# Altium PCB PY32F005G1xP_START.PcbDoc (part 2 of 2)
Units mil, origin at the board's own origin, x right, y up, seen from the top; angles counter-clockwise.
Board outline 1771.65 x 3929.06 mil, 2 copper layers (Top Layer, Bottom Layer), stack 21 mil thick; 129 components, 121 nets, 506 pads, 279 vias.
Unrouted connection lines stored in the file: 5.
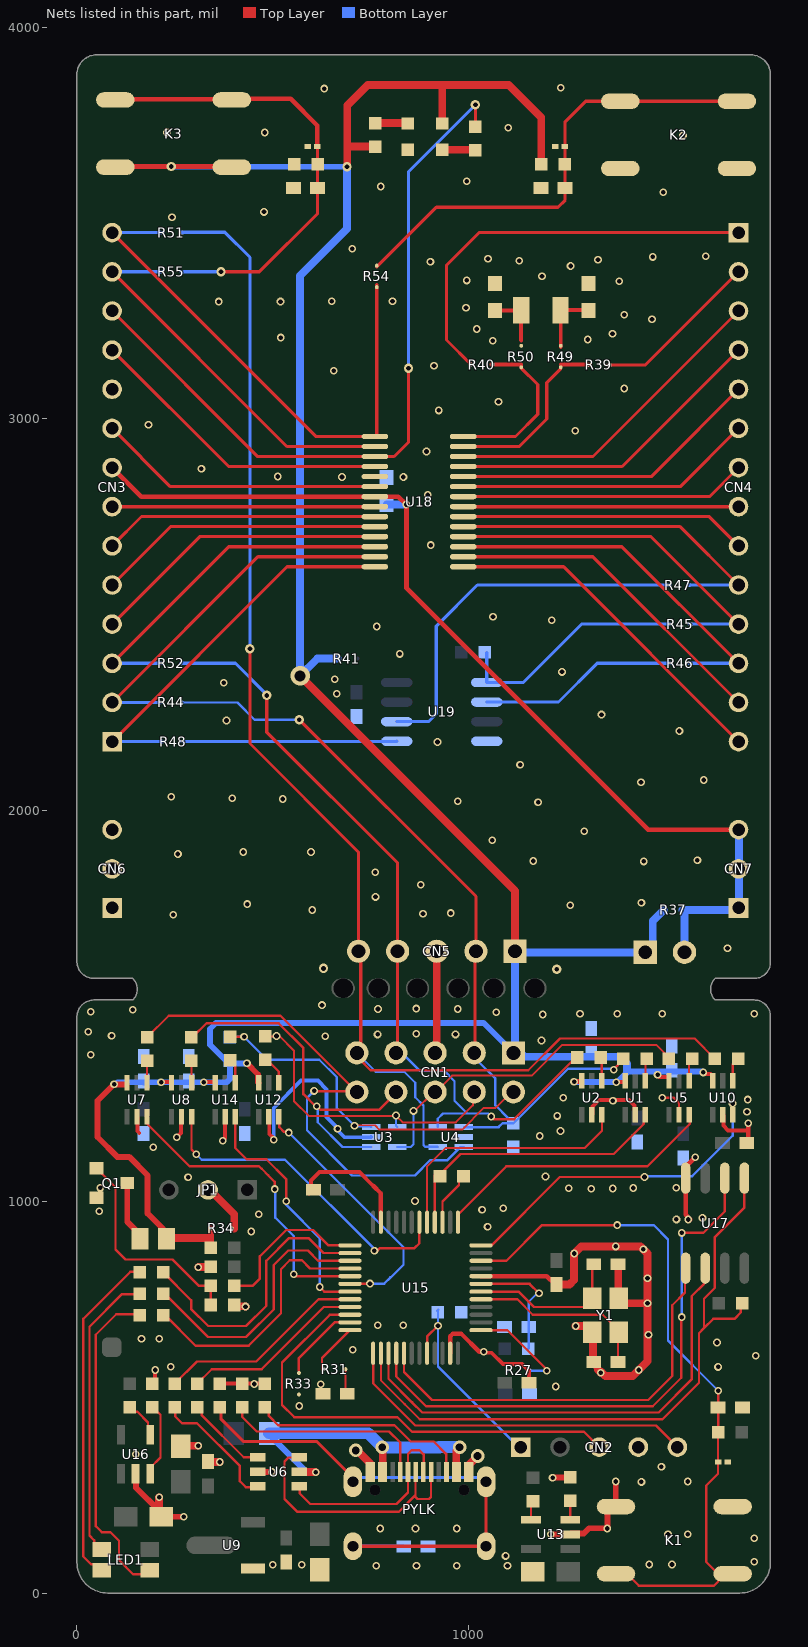
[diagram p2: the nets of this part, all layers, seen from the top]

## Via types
v1: diameter 19.68, hole 11.81, Top Layer to Bottom Layer, 140 vias
v2: diameter 19.68, hole 11.81, Top Layer to Bottom Layer, tented both sides, 114 vias
v3: diameter 24, hole 12, Top Layer to Bottom Layer, tented both sides, 12 vias
v4: diameter 35, hole 20, Top Layer to Bottom Layer, tented both sides, 8 vias
v5: diameter 30, hole 15, Top Layer to Bottom Layer, tented both sides, 2 vias
v6: diameter 40, hole 20, Top Layer to Bottom Layer, tented both sides, 2 vias
v7: diameter 50, hole 28, Top Layer to Bottom Layer, 1 vias

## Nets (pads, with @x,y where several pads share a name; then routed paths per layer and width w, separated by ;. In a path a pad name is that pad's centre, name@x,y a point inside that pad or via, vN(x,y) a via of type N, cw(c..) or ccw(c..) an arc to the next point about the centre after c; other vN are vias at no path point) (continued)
GND: C1.1 C2.1 C3.1 C4.1 C5.1 C6.1 C7.1 C8.1 C9.1 C10.1 C11.1 C12.1 C13.1 C14.1 C15.1 C16.1 C17.1 C18.1 C19.1 C20.1 C21.1 C22.1 C23.1 C24.1 C25.1 C26.1 C27.1 C28.1 C29.1 C30.2 C31.1 CN1.5 CN2.4 CN3.10 CN5.3 CN6.1 CN6.2 CN6.3 K1.3 K1.4 K2.3 K2.4 LED_VDD*.2 PYLK.A1 PYLK.A12 PYLK.B1 PYLK.B12 Q1.2 R1.1 R3.2 R5.1 R8.2 R20.1 R21.1 R25.1 R28.2 R30.1 R33.2 R56.1 U1.2 U2.2 U3.2 U4.2 U5.2 U6.2 U7.2 U8.2 U9.1 U10.2 U11.2 U12.2 U13.2 U14.2 U15.8 U15.23 U15.47 U16.2 U17.4 U18.5 U19.4 U20.2 U21.2 Y1.2 Y1.4 | length 4450.5
  Top Layer w6: v2(1495,1265) 1525,1265 1538.06,1251.94 U5.2@1538.06,1221.69
  Top Layer w10: U7.2@153.55,1216.69 154.54,1215.7 154.54,1180.08 159.36,1175.25 ; R30.1@200,540 v2(200,570) ; C16.1@210,210 210,200 C16.1@215,195 ; v2(255,1164.6) 265.89,1175.49 265.89,1215.32 U8.2@267.26,1216.69 ; C2.1@265,375 C2.1@270,380 ; C3.1@335,336 C3.1@336,335 ; R8.2@365,535 v2@453.95,535 ; v2(372.9,1155.7) 378.59,1161.39 U14.2@378.59,1216.59 ; R20.1@401.52,735.88 R20.1@403.04,737.4 ; v2(453.1,534.15) v2@453.95,535 ; R3.2@480,535 v2@453.95,535 ; U12.2@490.12,1216.69 491.41,1215.4 491.41,1172.62 501.83,1162.2 501.83,1156.83 v2@500,1155 ; C21.1@593.36,1020 603.36,1030 C21.1@604,1030 597.95,1036.05 597.95,1054.14 619.23,1075.42 721.98,1075.42 756.82,1040.58 ; C17.1@628.59,509.5 C17.1@629.59,510.5 ; PYLK.A1@743.31,309.89 PYLK.B12@755.12,309.89 ; PYLK.B1@995.28,309.89 PYLK.A12@1007.09,309.89 ; v2@1039.47,613.56 v2@1039.6,613.69 ; v2@1041.61,614.02 1059.36,614.02 1088.57,584.8 1137.07,584.8 1154.91,566.95 C20.1@1154.87,537.59 ; U2.2@1314.26,1220.75 1317.1,1223.58 1317.1,1242.95 1334.15,1260 v2@1370.02,1260 ; v2(1369.2,1257.6) 1370.02,1258.42 v2@1370.02,1260 ; U1.2@1426.64,1221.69 1424.75,1223.58 1424.75,1245.25 1410,1260 v2@1370.02,1260 ; U10.2@1649.49,1221.69 1651.38,1219.8 1651.38,1193.96 1663.61,1181.72 1715,1181.72
  Top Layer w11: 756.82,1040.58 776.42,1020.98 U15.23@776.42,947.32 ; U15.47@953.58,612.68 953.58,655.91 959.74,662.07 982.08,662.07 1027.87,616.28 v2(1039.35,616.28) ; U15.8@1032.32,809.53 1199.94,809.53 1221.47,788 C22.1@1225.12,788
  Top Layer w12: Q1.2@50.2,1009.8 Q1.2@55.01,1004.99 ; v2(1561.71,954.27) 1566.84,954.27 1555,966.11 1555,1088.88 1579.39,1113.27 v2(1579.39,1113.51) ; C18.1@1711,1150 1715,1154 1715,1181.72 v2(1715,1200)
  Top Layer w15: U16.2@149.48,304.48 150.91,303.04 150.91,269.09 C16.1@210,210 ; C16.1@215,195 v2(272.56,195) ; U6.2@470.66,310.05 472.24,308.47 473.29,309.52 v2(498.08,309.52) ; v2(1210,150) U13.2@1260,150 1262.16,152.16 1294.66,152.16 1308.23,165.74 v2@1354.26,165.74 ; v2(1215,295) R25.1@1260,295 ; v2(1355,165) 1355,209.44 1366.26,220.7 1376.55,220.7 v2(1376.55,285)
  Top Layer w20: C16.1@210,210 v2(210,245) ; C2.1@270,380 273.84,376.16 v2(310,376.16) ; v2(309.83,832.29) 310.59,833.04 341.17,833.04 R21.1@341.93,833.8 ; C3.1@336,335 v2(365,335) ; R20.1@403.04,737.4 403.04,737.12 407.52,732.64 429.94,732.64 v2(430.7,731.87) ; v4(712.08,364.5) 715.53,364.5 PYLK.A1@749.17,330.85 ; CN1.5@915,1380 919.26,1384.26 CN5.3@919.26,1639.56 ; PYLK.A12@1003.89,330.35 v4(1023.55,350) ; C22.1@1220.12,797 1225.12,792 C22.1@1225.12,788 1225.41,788.28 1258.41,788.28 1270.12,800 v2(1270.12,867.57) 1288.1,885.55 1439.57,885.55 1457.58,867.54 v2(1457.58,803.85) 1457.58,740.13 1457.58,592.46 v2(1435.12,570) 1419.85,554.73 1349.89,554.73 v2@1339.64,564.98 ; v2(1273.98,682.29) 1301.06,682.29 Y1.2@1316.66,666.69 1318.39,664.96 1318.39,591.73 C19.1@1320.12,590 1324.12,590 1329.12,585 1329.12,575.5 1330.37,574.25 ; 1330.37,570.63 v2(1337.83,563.18) ; C25.1@1382.12,840 1382.85,839.27 1382.85,754.04 Y1.4@1383.59,753.31 1396.74,740.16 v2(1457.55,740.16)
  Bottom Layer w6: v2@499.26,1157.83 v2(502.89,1157.83)
  Bottom Layer w10: v2(502.89,1157.83) 502.89,1239.49 572.46,1309.06 615.72,1309.06 638,1286.78 638,1215.79 665.89,1187.9 v2(665.89,1185.89) ; v2@665,1183 683.72,1164.28 750.81,1164.28 U3.2@751.54,1165
  Bottom Layer w20: CN1.5@915,1380 CN1.5@921,1386 ; CN5.3@919.26,1639.56 CN5.3@921,1637.82 ; CN5.3@921,1639.56 CN5.3@921,1642.94
  other v1: 500.23,72.73 574.48,72.72 568,478 1223.05,527.77 622.75,533.15 239.93,578.18 704.43,621.59 833.63,683.94 768.47,684.5 445.71,923.68 1049,936 1531.33,954.53 1597.76,958.38 464.86,967.62 1035,979 1089,983 863.55,1001.58 1313.59,1033.06 1368.58,1033.45 1256.66,1033.84 1421.24,1034.63 1530.67,1035.55 284,1062 1197,1064 195,1139 1235.29,1180.47 1227.19,1218.9 1711.69,1229.78 1713.32,1260.65 1186.59,1411.54 634,1422 88.6,1424 768,1427 967,1427 867,1429 29.3,1434.1 1190,1478 1071,1484 769,1492 973,1492 867,1493 626,1502 1661.98,1647.06 246,1733 884,1735 955,1737 601,1745 1260,1757 435,1760 1442,1763 762.85,1778.25 878,1809 761.85,1841.25 1448,1869 1166,1870 1585,1872 258,1888 425,1893 598,1893 1061,1923 1296,1946 1178,2020 973,2023 525.85,2028.25 397,2030 241,2034 1441,2071 1601,2077 1132,2116 921,2174 1539,2202 382,2229 1340,2244 664,2297 375,2325 659,2334 1239,2353 825,2399 766,2469 1213,2485 1063,2494 904,2677 896,2805 677,2851 834,2851 513,2852 318,2872 893,2916 1273,2969 183,2984 924,3021 1077,3043 1398,3077 656,3122 912,3135 1062,3199 1305,3202 521,3207 1368,3217 1021,3229 1469,3254 1398,3265 994,3283 362,3299 520,3299 651,3300 806,3300 1385,3351 996,3353 1188,3364 1261,3390 903,3401 1129.97,3403.49 1331,3406 1050,3408 1471,3413 1606,3415 703,3434 243,3514 478,3528 1498,3578 776,3593 996,3606 1548,3723 230,3731 480,3731 1102,3743 632,3843 1236,3845
  other v2: 765,70 867.5,70 970,70 1100,70 1462.25,73 1520,73 1730,80 1095,95 1730,140 1510,150 1560,150 775,165 865,165 970,165 1442,284 1560,285 1493,323 150,355 1637.74,577.74 1734,606 1635,640 165,650 210,650 1460.12,660 1447.03,878.1 1376.26,885.55 57.3,975.34 60,1035 1182.35,1167.57 1241.94,1264.95 35,1375 1285,1480 1380,1480 1495,1480 1730,1480 35,1485 143,1490
  other v3: 1226,1593.58 630,1595.58
L_USB_CN_DM: PYLK.A7 PYLK.B7 U6.4 | length 510.1
  Top Layer w6: U6.4@568.15,272.6 569.18,271.57 569.18,254.46 596.04,227.6 816.36,227.6 845.67,256.9 845.67,355.67 855,365 875,365 885.71,354.29 885.71,310.57 PYLK.A7@885.04,309.89
L_USB_CN_DP: PYLK.A6 PYLK.B6 U6.6 | length 675.9
  Top Layer w6: U6.6@568.15,347.4 567.26,346.51 540.39,346.51 530.35,336.47 530.35,240.4 563.22,207.53 822.27,207.53 864.95,250.21 ; PYLK.A6@864.95,309.48 864.95,250.21 ; PYLK.B6@904.31,309.48 904.31,245.56 899.06,240.31 870.05,240.31 864.95,245.41 864.95,250.21
LED_BLUE: R9.2 U15.28 | length 675.2
  Top Layer w6: R9.2@220,710 225.04,710 303.26,631.77 438.53,631.77 521.33,714.58 521.33,827.41 543.92,850 575,850 595.79,829.21 U15.28@697.68,829.21
LED_GREEN: R6.2 U15.26 | length 724.3
  Top Layer w6: R6.2@220,820 291.82,748.18 291.82,725.67 335.36,682.13 432.27,682.13 483.48,733.34 483.48,848.48 541.75,906.75 591.91,906.75 630.07,868.58 U15.26@697.68,868.58
LED_RED: R4.2 U15.27 | length 692.2
  Top Layer w6: R4.2@220,765 224.07,765 335.03,654.04 432.13,654.04 502.68,724.59 502.68,837.68 540,875 590,875 616.1,848.9 U15.27@697.68,848.9
NetC1_2: C1.2 PYLK.1 PYLK.2 PYLK.3 PYLK.4 R8.1 | length 1425.4
  Top Layer w8: R8.1@365,475 368.29,471.71 368.29,443.87 424.64,387.52 611.97,387.52 705.12,294.37 PYLK.1@705.12,284.29 ; PYLK.3@705.12,119.73 PYLK.4@1045.28,119.73 PYLK.2@1045.28,284.29
  Bottom Layer w8: PYLK.3@705.12,119.73 834.27,119.73 C1.2@835,119 ; PYLK.1@716.04,295.21 PYLK.2@1034.36,295.21
  Bottom Layer w20: PYLK.1@705.12,284.29 PYLK.1@716.04,295.21 ; PYLK.2@1034.36,295.21 PYLK.2@1045.28,284.29
NetC17_2: C17.2 R31.2 | length 64.1
  Top Layer w6: R31.2@686.21,571.75 686.21,513.88 C17.2@690.59,509.5
NetC28_2: C28.2 K2.1 K2.2 R42.2 R54.1 U20.1 | length 1213.2
  Top Layer w8: R54.1@766,3387.75 918.25,3540 1229,3540 1247,3558 C28.2@1247,3589 1247,3649 R42.2@1246,3650 1246.3,3650.3 U20.1@1246.3,3695 1246.3,3757.3 1299.7,3810.7 K2.1@1388,3810.7 K2.2@1686,3810.7
NetC29_2: C29.2 R49.1 Y2.1 | length 165.9
  Top Layer w10: R49.1@1236,3182.76 1236,3276.2 Y2.1@1235.2,3277 C29.2@1306.5,3277
NetC30_1: C30.1 R50.1 Y2.2 | length 144.1
  Top Layer w10: C30.1@1068,3276.5 1134.3,3276.5 Y2.2@1134.81,3277 1134.81,3200.19 1135,3200
NetC31_2: C31.2 K3.3 K3.4 R55.1 R56.2 U21.1 | length 1188.1
  Top Layer w8: v3(368,3375) 466,3375 615,3524 C31.2@615,3589 R56.2@615,3650 U21.1@615,3695
  Top Layer w12: K3.4@92,3815.59 390,3815.59 391.76,3817.35 545.65,3817.35 614.3,3748.7 U21.1@614.3,3695
  Bottom Layer w8: R55.1@264.75,3375 v3(368,3375)
NetCN4_1: CN4.1 R40.2 | length 1060.5
  Top Layer w8: R40.2@1007,3138 944,3201 944,3392 1027,3475 CN4.1@1690,3475
NetCN4_2: CN4.2 R39.2 | length 434.6
  Top Layer w8: R39.2@1354.03,3136.97 1451.97,3136.97 CN4.2@1690,3375
NetLED1_2: LED1.2 R9.1 | length 846.1
  Top Layer w6: R9.1@160,710 157.67,712.33 100.33,712.33 48,660 48,171 63.8,155.2 85.86,155.2 107.53,133.53 107.53,84.16 143.82,47.87 175.08,47.87 LED1.2@186.02,58.82
NetLED1_3: LED1.3 R6.1 | length 884.3
  Top Layer w6: LED1.3@44.28,58.52 LED1.3@58.98,43.82 ; LED1.3@63.98,58.82 49.28,73.52 36.09,73.52 16,93.61 16,700.34 136.59,820.93 159.07,820.93 R6.1@160,820
NetLED1_4: LED1.4 R4.1 | length 755.1
  Top Layer w6: LED1.4@56.66,98.5 44.36,110.81 44.36,134.74 32,147.09 32,680.34 115.39,763.73 158.73,763.73 R4.1@160,765
NetLED_PA1_2: LED_PA1.2 R53.1 | length 84
  Top Layer w20: LED_PA1.2@933,3687 R53.1@1017,3687
NetLED_VDD*_1: LED_VDD*.1 R38.1 | length 83
  Top Layer w20: R38.1@762,3754.89 LED_VDD*.1@845,3754.89
NetPYLK_A5: PYLK.A5 R1.2 | length 530.3
  Top Layer w6: R1.2@422.49,474.99 422.49,449.82 459.51,412.79 797.58,412.79 825.99,384.38 PYLK.A5@825.99,309.89
NetPYLK_B5: PYLK.B5 R3.1 | length 566
  Top Layer w6: R3.1@480,475 490.31,464.69 490.31,452.34 513.85,428.8 811.11,428.8 852.66,387.24 911.55,387.24 943.17,355.62 943.17,310.82 PYLK.B5@944.1,309.89
NetQ1_1: Q1.1 R19.1 R20.2 | length 559
  Top Layer w6: Q1.1@50,1084.8 51.97,1084.8 63.72,1073.06 63.72,1071.23 98.46,1036.49 98.46,877.34 123.86,851.94 244.45,851.94 311.61,784.78 R19.1@341.53,784.78 ; R20.2@341.52,735.88 R19.1@341.52,784.77
NetQ1_3: Q1.3 R15.1 | length 166.5
  Top Layer w6: Q1.3@125.49,1044.15 Q1.3@128.74,1047.4 ; R15.1@161.54,905 R15.1@161.54,910.91
  Top Layer w15: Q1.3@128.74,1047.4 128.74,948.28 161.54,915.49 R15.1@161.54,905
NetR2_1: R2.1 U1.4 | length 57.9
  Top Layer w6: U1.4@1452.23,1308.31 1452.23,1362.02 R2.1@1455.21,1365
NetR7_1: R7.1 U2.4 | length 57.8
  Top Layer w6: R7.1@1338.06,1365 1340.8,1362.27 U2.4@1340.8,1308.31
NetR10_1: R10.1 U5.4 | length 60.3
  Top Layer w6: U5.4@1563.66,1308.31 1563.66,1356.3 R10.1@1572.35,1365
NetR11_1: R11.1 U6.3 | length 332.9
  Top Layer w6: R11.1@250,475 250.77,474.23 250.77,451.69 268.41,434.05 306.8,434.05 416.24,324.61 416.24,285.87 431.63,270.48 459.74,270.48 U6.3@461.53,272.28
NetR12_1: R12.1 U6.1 | length 227.7
  Top Layer w6: R12.1@308.75,480 319.15,469.6 319.15,453.68 426,346.83 U6.1@471.97,346.83
NetR13_1: R13.1 U7.4 | length 59
  Top Layer w6: R13.1@173.55,1360 179.14,1354.41 U7.4@179.14,1303.31
NetR14_1: R14.1 U8.4 | length 60.8
  Top Layer w6: R14.1@280.94,1360.02 R14.1@290.82,1350.14 ; U8.4@292.85,1303.31 R14.1@292.86,1350.12
NetR18_1: R18.1 U10.4 | length 62.7
  Top Layer w6: U10.4@1675.08,1308.31 1675.08,1350.59 R18.1@1689.49,1365
NetR22_1: R22.1 U12.4 | length 75.3
  Top Layer w6: R22.1@481.63,1362.11 485.62,1362.11 515.71,1332.03 U12.4@515.71,1303.31
NetR24_2: R24.2 U13.4 | length 49.6
  Top Layer w6: U13.4@1160,187.5 1160,230 R24.2@1165,235
NetR25_2: R25.2 U13.3 | length 47.5
  Top Layer w6: U13.3@1260,187.5 R25.2@1260,235
NetR26_1: R26.1 U14.4 | length 62.8
  Top Layer w6: R26.1@391.2,1360.7 404.28,1347.62 U14.4@404.28,1303.31
NetR27_2: R27.2 U15.1 | length 263.8
  Top Layer w6: U15.1@1032.32,671.73 1099.27,671.73 1200,571 v1(1200,568)
  Bottom Layer w6: R27.2@1149.03,569.03 1150.05,568 v1(1200,568)
NetR29_2: R29.2 U16.4 | length 96.1
  Top Layer w6: R29.2@135,475 147,463 154.44,463 181.5,435.94 181.5,411 U16.4@187.5,405
NetR30_2: R30.2 U16.3 | length 190
  Top Layer w6: U16.3@187.5,305 187.5,320 213.56,346.06 213.56,455.68 207.24,462 206,462 R30.2@193,475
NetR31_1: R31.1 U15.36 | length 129.6
  Top Layer w6: R31.1@626.21,571.75 626.21,600.26 U15.36@697.68,671.73
NetR33_1: R33.1 U15.35 | length 201.4
  Top Layer w6: 566.96,567.4 566.96,600.38 658,691.42 U15.35@697.68,691.42
NetR43_1: R43.1 R45.1 U19.1 | length 609
  Bottom Layer w8: R43.1@1047,2403 U19.1@1047,2326 1140,2326 1289,2475 R45.1@1517.24,2475
NetR46_1: R46.1 U19.2 | length 511.2
  Bottom Layer w8: U19.2@1047,2276 1230,2276 1329,2375 R46.1@1517.24,2375
NetR47_2: R47.2 U19.6 | length 974.7
  Bottom Layer w8: U19.6@817,2226 898,2226 918,2246 918,2470 1022.97,2574.97 R47.2@1515.97,2574.97
NetR48_2: R48.2 U19.5 | length 551.4
  Bottom Layer w8: R48.2@266.02,2175.03 816.02,2175.03 U19.5@817,2176
OSCIN32: R39.1 R49.2 U18.27 | length 459.2
  Top Layer w8: U18.27@986.83,2928.75 1129.75,2928.75 1200,2999 1200,3092 R49.2@1235.5,3127.5
  Top Layer w10: R49.2@1235.97,3137.98 1308.27,3137.98 R39.1@1309.25,3137
OSCOUT32: R40.1 R50.2 U18.28 | length 434.3
  Top Layer w8: U18.28@986.83,2954.34 1120.34,2954.34 1177,3011 1177,3087 1134.96,3129.04 R50.2@1134.97,3137.98
  Top Layer w10: R40.1@1058.75,3138 R50.2@1134.97,3137.98
PA0: CN3.13 R55.2 U18.2 | length 986
  Top Layer w8: CN3.13@90,3375 536.25,2928.75 U18.2@761.18,2928.75
  Bottom Layer w8: CN3.13@90,3375 R55.2@219.97,3374.97
PA1: CN3.12 R53.2 U18.3 | length 1915.4
  Top Layer w8: CN3.12@90,3275 462,2903 U18.3@761.18,2903 ; U18.3@761.18,2903.16 810.16,2903.16 847.31,2940.31 847.31,3036.69 847,3037 v3(847,3129) ; R53.2@1018,3746 v3(1018,3802)
  Bottom Layer w8: v3(847,3129) 847,3631 v3(1018,3802)
PA2: CN3.11 U18.4 | length 794.4
  Top Layer w8: CN3.11@90,3175 387.43,2877.57 U18.4@761.18,2877.57
PA3: CN3.9 U18.6 | length 732.7
  Top Layer w8: CN3.9@90,2975 238.61,2826.39 U18.6@761.18,2826.39
PA4: CN3.7 U18.8 | length 671.2
  Top Layer w8: CN3.7@90,2775 U18.8@761.18,2775
PA5: CN3.6 U18.9 | length 704.3
  Top Layer w8: CN3.6@90,2675 165,2750 U18.9@763.24,2750
PA6: CN3.5 U18.10 | length 726.6
  Top Layer w8: CN3.5@90,2575 239,2724 U18.10@754.88,2724
PA7: CN3.4 U18.11 | length 763.7
  Top Layer w8: CN3.4@90,2475 313.43,2698.43 U18.11@761.18,2698.43
PB0: CN4.10 R47.1 U18.19 | length 894.1
  Top Layer w8: U18.19@986.83,2724.02 1540.98,2724.02 CN4.10@1690,2575
  Bottom Layer w8: R47.1@1560.75,2575 CN4.10@1690,2575
PB1: CN4.11 R45.2 U18.18 | length 923.7
  Top Layer w8: U18.18@986.83,2698.43 1466.57,2698.43 CN4.11@1690,2475
  Bottom Layer w8: R45.2@1562.02,2475.03 CN4.11@1690,2475
PB2: CN4.12 R46.2 U18.17 | length 954.5
  Top Layer w8: U18.17@986.83,2672.84 1392.16,2672.84 CN4.12@1690,2375
  Bottom Layer w8: R46.2@1562.02,2375.03 CN4.12@1690,2375
PB3: CN3.1 R48.1 U18.14 | length 987.4
  Top Layer w8: CN3.1@90,2175 536.66,2621.66 U18.14@761.18,2621.66
  Bottom Layer w8: CN3.1@90,2175 R48.1@221.24,2175
PB4: CN4.14 U18.15 | length 888.2
  Top Layer w8: U18.15@986.83,2621.66 1243.34,2621.66 CN4.14@1690,2175
PB5: CN4.13 U18.16 | length 857.4
  Top Layer w8: U18.16@986.83,2647.25 1317.75,2647.25 CN4.13@1690,2275
PC0-NRST: CN3.14 R51.2 R54.2 U18.1 | length 1409.9
  Top Layer w8: CN3.14@90,3475 611,2954 U18.1@761.18,2954 ; U18.1@761.18,2954.34 763.43,2954.34 765.97,2956.88 R54.2@765.97,3342.97
  Bottom Layer w8: CN3.14@90,3475 R51.2@220.97,3474.97
PC1: CN4.3 U18.26 | length 857.2
  Top Layer w8: U18.26@986.83,2903.16 1318.16,2903.16 1391,2976 CN4.3@1690,3275
PC2: CN4.4 U18.25 | length 826.4
  Top Layer w8: U18.25@986.83,2877.57 1392.57,2877.57 1441,2926 CN4.4@1690,3175
PC3: CN4.5 U18.24 | length 795.5
  Top Layer w8: U18.24@986.83,2851.98 1466.98,2851.98 1491,2876 CN4.5@1690,3075
PC4: CN4.6 U18.23 | length 764.7
  Top Layer w8: U18.23@986.83,2826.39 1541.39,2826.39 CN4.6@1690,2975
PC5: CN4.7 U18.22 | length 733.9
  Top Layer w8: U18.22@986.83,2800.8 1615.8,2800.8 CN4.7@1690,2875
PC6: CN4.8 U18.21 | length 700
  Top Layer w8: U18.21@990,2775 CN4.8@1690,2775
PC7: CN4.9 U18.20 | length 734.1
  Top Layer w8: U18.20@986.83,2749.61 1615.39,2749.61 1689.5,2675.5 CN4.9@1690,2675
PYLK_BOOT0: CN2.1 R28.1 U15.44 | length 514.4
  Top Layer w6: U15.44@894.53,612.68 894.53,655.07 v2(922.21,682.75)
  Bottom Layer w6: R28.1@923.26,724.4 920.49,721.63 922.21,719.9 v2(922.21,682.75) 922.21,578.79 CN2.1@1124,377
PYLK_KEY: C6.2 K1.1 K1.2 R16.1 U11.1 U15.10 | length 1804.3
  Top Layer w6: U15.10@1032.32,848.9 1097.14,848.9 1188.24,940 v2(1380,940) ; K1.2@1376.55,49 1405.25,49 1435.5,18.75 1627.36,18.75 1639.02,30.41 1639.02,34.51 K1.1@1653.51,49 ; v2(1638,517) C6.2@1638,474 R16.1@1638,411 1637.7,410.7 U11.1@1637.7,335 1637.7,304.7 1607.3,274.3 1607.3,80 1638.3,49 K1.1@1653.51,49 ; K1.1@1674.55,49 K1.1@1653.51,49
  Bottom Layer w6: v2(1380,940) 1473.52,940 1510,903.52 1510,645 v2(1638,517)
PYLK_NRST: C24.2 R36.1 U15.7 | length 313.8
  Top Layer w6: U15.7@1032.32,789.84 1156.36,789.84 v2(1180.4,765.8)
  Bottom Layer w6: R36.1@1153,624 1154.12,625.12 C24.2@1154.12,680 1154.12,744 1175.92,765.8 v2(1180.4,765.8)
PYLK_OSCIN: C19.2 U15.5 Y1.3 | length 465.6
  Top Layer w6: U15.5@1032.32,750.47 1125.05,750.47 1164.42,711.1 1343.11,711.1 1383.59,670.63 Y1.3@1383.59,666.69 1382.12,665.22 C19.2@1382.12,590
PYLK_OSCOUT: C25.2 U15.6 Y1.1 | length 399.8
  Top Layer w6: U15.6@1032.32,770.16 1127.99,770.16 1167.36,730.79 1297.03,730.79 1316.66,750.41 Y1.1@1316.66,753.31 1316.66,836.54 C25.2@1320.12,840
PYLK_SPI_CS: R35.1 U15.38 U17.1 | length 1667.6
  Top Layer w5: U15.38@776.42,612.68 776.42,543.62 837.66,482.38
  Top Layer w6: 837.66,482.38 875.95,444.09 1495.51,444.09 1588.88,537.47 1588.88,663.88 1601.77,676.77 ; R35.1@1700,740 1695.62,735.62 1695.62,716.69 1679.36,700.42 1625.42,700.42 1601.77,676.77 ; U17.1@1705,1060 1705,985 1629.69,909.69 1629.69,780.01 1601.77,752.09 1601.77,676.77
PYLK_SPI_MISO: U15.40 U17.2 | length 1437.2
  Top Layer w6: U15.40@815.79,612.68 815.79,553.3 891.8,477.3 1471,477.3 1543.9,550.2 1543.9,703.9 v2(1545,705) ; v2(1545,920) 1600,920 1655,975 U17.2@1655,1060
  Bottom Layer w6: v2(1545,705) v2(1545,920)
PYLK_SPI_MOSI: U15.41 U17.5 | length 1077.9
  Top Layer w6: U15.41@835.47,612.68 835.47,564.49 906.66,493.3 1459.42,493.3 1520.53,554.41 1520.53,735.09 1553.13,767.69 1553.13,828.13 U17.5@1555,830
PYLK_SPI_SCK: U15.39 U17.6 | length 1208.9
  Top Layer w6: U15.39@796.1,612.68 796.1,547.36 856.32,487.14 882.17,461.3 1486.07,461.3 1570.21,545.44 1570.21,758.06 1601.94,789.79 1601.94,826.94 U17.6@1605,830
SWCLK: CN3.3 R52.2 U18.12 | length 924.5
  Top Layer w8: CN3.3@90,2375 387.84,2672.84 U18.12@761.18,2672.84
  Bottom Layer w8: CN3.3@90.03,2374.97 R52.2@219.97,2374.97
SWD_SCK: CN2.5 U15.37 | length 921.6
  Top Layer w6: U15.37@756.73,612.68 756.73,535.75 864.48,428 1479,428 CN2.5@1534,373
SWD_SDA: CN2.3 U15.34 | length 1187.1
  Top Layer w6: U15.34@697.68,711.1 646.11,711.1 524.05,589.04 524.05,480.71 555.57,449.2 818.75,449.2 855.95,412 1295,412 CN2.3@1334,373
SWDIO: CN3.2 R44.2 U18.13 | length 955.4
  Top Layer w8: CN3.2@90,2275 462.25,2647.25 U18.13@761.18,2647.25
  Bottom Layer w8: CN3.2@90,2275 R44.2@219.97,2274.97
T_RESET: CN1.9 CN5.5 R18.2 R51.1 U4.4 | length 3737
  Top Layer w6: CN1.9@715,1380 CN1.9@725,1390 ; CN5.5@719.26,1639.56 CN5.5@725,1633.82 ; CN1.9@722.78,1362.78 750.2,1335.36 1152.91,1335.36 1233.99,1416.44 1578.06,1416.44 R18.2@1629.49,1365
  Top Layer w8: v3(442,2412) 442,2170 719.26,1892.74 CN5.5@719.26,1639.56 ; CN1.9@725,1390 CN5.5@725,1633.82
  Bottom Layer w6: CN1.9@715,1380 763.22,1331.78 836.02,1331.78 864.1,1303.69 864.1,1266.42 885.15,1245.37 885.15,1144.31 889.61,1139.85 921.09,1139.85 U4.4@921.54,1139.41
  Bottom Layer w8: R51.1@264.75,3476 378,3476 442,3412 v3(442,2412) ; CN1.9@715,1380 CN1.9@724.04,1389.04 ; CN5.5@719.26,1639.56 CN5.5@724.15,1644.45
T_RESETa: U10.3 U15.12 | length 870.1
  Top Layer w6: U15.12@1032.32,888.27 1058.79,888.27 1233.47,1062.96 1321.53,1062.96 v2(1449.91,1062.96) ; v2(1674.82,1250.7) 1675.08,1250.44 U10.3@1675.08,1221.69
  Bottom Layer w6: v2(1449.91,1062.96) 1451.65,1064.7 1571.4,1064.7 1674.82,1168.11 v2(1674.82,1250.7)
T_RTCK_DTRa: U5.3 U15.13 | length 731.2
  Top Layer w6: U15.13@973.27,947.32 973.27,966.57 1096.7,1090 1456.99,1090 1565.18,1198.19 1565.18,1220.16 U5.3@1563.66,1221.69
T_RTCK_VCP_DTR: CN1.6 R10.2 U3.5 | length 868.3
  Top Layer w5: v2(859.81,1231.67) 863.24,1231.67 911.57,1280 CN1.6@915,1280 916.63,1280 958.49,1321.86 1161.73,1321.86 1240.3,1400.44 1479.98,1400.44 1500.35,1380.07 1500.35,1377 R10.2@1512.35,1365
  Bottom Layer w6: U3.5@818.46,1139.41 852.51,1139.41 859.81,1146.71 v2(859.81,1231.67)
T_TCK_SWCLK: CN1.7 CN5.4 R7.2 R52.1 U4.5 | length 2038.8
  Top Layer w6: v2(1058.5,1217.32) 1065.14,1210.69 1116.96,1210.69 1271.28,1365 R7.2@1278.06,1365
  Top Layer w8: v3(485,2293) 485,2199 819.26,1864.74 CN5.4@819.26,1639.56 819.26,1384.26 CN1.7@815,1380
  Bottom Layer w6: CN1.7@822.5,1387.5 875.47,1334.53 937.65,1334.53 964.6,1307.57 964.6,1257.54 997.14,1225 ; U4.5@921.54,1190.59 921.54,1211.54 935,1225 997.14,1225 ; v2(1058.5,1217.32) 1050.82,1225 997.14,1225
  Bottom Layer w8: R52.1@264.75,2375 405.07,2375 485,2295.07 v3(485,2293) ; CN1.7@815,1380 CN1.7@817.79,1382.79 ; CN5.4@817.79,1638.1 CN5.4@819.26,1639.56
T_TCK_SWCLKa: U2.3 U15.17 | length 668.1
  Top Layer w5: U15.17@894.53,947.32 894.53,1089.76 941.77,1137
  Top Layer w6: 941.77,1137 1047.62,1137 1297.43,1137 1341.41,1180.98 1341.41,1221.08 U2.3@1340.8,1221.69
T_TDI_VCP_TX: CN1.4 R22.2 U3.4 | length 783.1
  Top Layer w5: R22.2@481.63,1422.11 517.9,1422.11 554.54,1385.48 554.54,1256.62 592.29,1218.86 v2@815,1218.86 ; R22.2@481.63,1425.11 R22.2@483.13,1423.61 ; v2@815.02,1218.86 831.78,1202.11 967.76,1202.11 1011.56,1245.9 1011.56,1276.56 CN1.4@1015,1280
  Bottom Layer w5: v2@815.06,1219.94 815.06,1194 U3.4@818.46,1190.59
  other v1: 509.96,1422.98
  other v2: 815,1220
T_TDI_VCP_TXa: U12.3 U15.30 | length 672.4
  Top Layer w6: U12.3@515.71,1216.69 516.93,1215.47 516.93,1190.37 529.24,1178.06 539.56,1178.06 v2(541.31,1176.31) ; U15.30@697.68,789.84 748.02,789.84 v2(748.76,790.58)
  Bottom Layer w6: v2(541.31,1176.31) 834.09,883.53 834.09,838.92 801.56,806.38 800.71,806.38 784.91,790.58 v2(748.76,790.58)
T_TDO_SWO: CN1.10 R13.2 U4.3 | length 1333.3
  Top Layer w6: R13.2@179.66,1420.08 234.47,1474.9 520.1,1474.9 CN1.10@708.51,1286.49 ; v2(605.87,1282.75) 606.54,1282.08 704.1,1282.08 CN1.10@708.51,1286.49 ; CN1.10@715,1280 CN1.10@708.51,1286.49
  Bottom Layer w6: v2(605.87,1282.75) 587.83,1264.72 587.83,1182.08 703.06,1066.86 863.29,1066.86 902.42,1105.99 946.45,1105.99 979.88,1139.41 U4.3@988.46,1139.41 U4.3@986.15,1137.1
T_TDO_SWOa: U7.3 U15.29 | length 807.7
  Top Layer w6: U7.3@179.14,1216.69 179.14,1198.86 287.46,1090.54 465.08,1090.54 471.63,1084 472.01,1084 489,1067.01 489,1066.63 504.93,1050.7 504.93,1032.69 v2(505.62,1032) ; v2(553.88,814.33) 558.68,809.53 641.55,809.53 U15.29@697.68,809.53
  Bottom Layer w6: v2(505.62,1032) 506.95,1030.68 506.95,958.93 553.88,912 v2(553.88,814.33)
T_TMS_SWDIO: CN1.3 CN5.2 R2.2 R5.2 R44.1 U4.1 | length 2040.9
  Top Layer w6: CN1.3@1015,1380 CN1.3@1017.13,1382.13 ; CN5.2@1017.13,1637.43 CN5.2@1019.26,1639.56 ; CN1.3@1019.37,1366.19 CN1.3@1025.56,1360 ; v2@1371.62,1338.31 1382.21,1348.9 1382.21,1352 R2.2@1395.21,1365
  Top Layer w8: v3(568,2231) 1019.26,1779.74 CN5.2@1019.26,1639.56 ; CN1.3@1017.13,1382.13 CN5.2@1017.13,1637.43
  Bottom Layer w6: R44.1@264.75,2275 410,2275 454,2231 v3(568,2231) ; U4.1@988.77,1190.29 1077.29,1190.29 1087,1200 R5.2@1115,1200 1254.25,1339.25 1369.25,1339.25 v2(1371.43,1337.07) ; CN1.3@1015,1380 CN1.3@1019,1384 ; CN5.2@1019,1639.3 CN5.2@1019.26,1639.56 ; CN5.2@1019,1639.56 CN5.2@1019,1644.94 ; CN1.3@1023.59,1359.7 1068.86,1314.42 1068.86,1246.14 R5.2@1101.08,1213.92
T_TMS_SWDIOa: R32.1 U1.3 U15.16 | length 723.8
  Top Layer w6: U15.16@914.21,947.32 R32.1@914.21,1067.37 ; R32.1@927.46,1064.37 927.46,1068.99 980.12,1121.65 1036.7,1121.65 1371.22,1121.65 1448.34,1198.77 1448.34,1217.8 U1.3@1452.23,1221.69
T_TMS_SWDIOa_OUT: R32.2 U15.15 | length 143.2
  Top Layer w6: U15.15@933.9,947.32 933.9,1000.64 975.82,1042.56 R32.2@975.82,1073.16
T_TRST_RTSa: U8.3 U15.18 | length 840.3
  Top Layer w6: U8.3@292.85,1216.69 292.86,1132.86 v2(304.82,1120.9) ; v2(759.92,874.35) 763.83,870.44 774.54,881.16 862.39,881.16 874.84,893.6 U15.18@874.84,947.32
  Bottom Layer w6: v2(304.82,1120.9) 318.81,1106.91 531.65,1106.91 759.92,878.64 v2(759.92,874.35)
T_TRST_VCP_RTS: CN1.8 R14.2 U3.1 | length 935
  Top Layer w6: R14.2@292.3,1420.1 295.54,1420.1 331.24,1455.8 515.25,1455.8 578.58,1392.47 578.58,1274.56 609.4,1243.73 v2(612.86,1243.73) 621.6,1235 772.67,1235 820,1282.33 CN1.8@820,1290
  Bottom Layer w6: v2(612.86,1243.73) 615,1241.6 615,1202.6 678.19,1139.41 U3.1@751.54,1139.41
T_VCP_RX: CN1.2 R23.1 R26.2 U3.3 | length 1000.9
  Top Layer w5: v2(708.97,1193.74) 710.23,1195 761.42,1195 772.45,1183.97 983.91,1183.97 1039.3,1239.36 1069.36,1239.36 CN1.2@1120,1290
  Top Layer w6: R26.2@391.2,1420.7 426.7,1420.7 v1(427,1421) ; R26.2@391.2,1431.85 R26.2@391.32,1431.97
  Bottom Layer w6: R23.1@391,1420 392,1421 v1(427,1421) 485.72,1362.28 619.26,1362.28 664.05,1317.5 664.05,1238.66 v2(708.97,1193.74) 708.23,1193 708.23,1191.77 750.36,1191.77 U3.3@751.54,1190.59
T_VCP_RXa: U14.3 U15.31 | length 636
  Top Layer w6: U14.3@404.28,1216.69 404.28,1137.29 433.27,1108.3 483.54,1108.3 534.4,1057.43 534.4,1001.38 v2(535,1000.78) ; v2(620.4,781.75) 631.99,770.16 U15.31@697.68,770.16
  Bottom Layer w6: v2(535,1000.78) 535,991.42 620.4,906.02 v2(620.4,781.75)
TVDD: C12.2 C13.2 C14.2 C15.2 CN1.1 CN5.1 JP2.1 K3.1 K3.2 LED_PA1.1 R15.2 R17.2 R23.2 R34.2 R37.1 R38.2 R41.1 R42.1 U1.6 U2.6 U5.6 U7.6 U8.6 U10.6 U12.6 U14.6 | length 7774.8
  Top Layer w6: U8.6@241.67,1303.31 U8.6@244.56,1306.2 ; U14.6@353.1,1303.31 U14.6@355.99,1306.2
  Top Layer w10: v2(215,1305) 239.98,1305 U8.6@241.67,1303.31 ; v1@325,1305 351.41,1305 U14.6@353.1,1303.31 ; v1(1377.88,1305.09) 1399.07,1305.09 1399.16,1305 1401.05,1306.89 U1.6@1401.05,1308.31 ; v2(1483.29,1324.06) 1488.61,1318.74 1512.47,1318.74 U5.6@1512.47,1308.31 ; v2@1608.68,1326.1 1618.91,1326.1 1623.9,1321.1 U10.6@1623.9,1308.31
  Top Layer w12: K3.2@92,3643.89 v3(241,3643.89) K3.1@390,3643.89 ; v2@1270.9,1306.9 U2.6@1289.01,1306.9
  Top Layer w15: v2(95,1300) 52.5,1257.5 52.5,1164.78 103.07,1114.2 133.42,1114.2 180.53,1067.09 180.53,969.95 220.52,929.96 220.52,912.95 R15.2@228.46,905 R15.2@230.24,906.78 ; v2@95.63,1299.37 U7.6@127.35,1299.37 ; 338.07,906.78 342.08,902.77 ; R17.2@342.08,874.02 342.08,902.77 ; R34.2@342.08,931.52 342.08,902.77 ; v1(434.28,1353.05) 462.84,1324.49 462.84,1305 U12.6@464.53,1303.31 ; v2(1270,1306) v2@1270.9,1306.9
  Top Layer w20: R15.2@230.24,906.78 338.07,906.78 ; v7(570,2343) 1119.26,1793.74 CN5.1@1119.26,1639.56 ; v3(690,3643) 690.77,3643.77 690.77,3694.89 ; R38.2@762,3694.89 690.77,3694.89 ; LED_PA1.1@933,3754 933,3852 ; R42.1@1186,3650 1186,3769 1103,3852 933,3852 ; 690.77,3694.89 690.77,3799.77 743,3852 933,3852
  Bottom Layer w15: v2(95,1300) 98.79,1300 103.67,1304.88 C15.2@168.87,1304.88 ; C15.2@170,1303.74 C15.2@168.87,1304.88 ; v2@214.88,1304.88 C15.2@168.87,1304.88 ; v2(215,1305) v1(323.77,1305) 383,1305 391,1313 R23.2@391,1360 380.76,1360 340,1400.76 340,1441 355,1456 1039,1456 CN1.1@1115,1380 ; v3(241,3643.89) 241.44,3643.44 689.56,3643.44 v3(690,3643) ; R23.2@391,1353.05 v1(434.28,1353.05) ; v2@1270.38,1305.62 v1@1377.36,1305.62 ; v1(1377.88,1305.09) 1379.15,1305.09 1381.49,1307.43 1382.09,1307.43 1406.58,1331.92 ; 1404.72,1331.92 1598.08,1331.92 v2(1600,1330)
  Bottom Layer w20: R41.1@665.25,2387 614,2387 v7(570,2343) 570,3365 690,3485 v3(690,3643) ; CN1.1@1118.94,1383.94 CN5.1@1118.94,1639.24 ; CN1.1@1122.04,1388.26 1143.46,1370 1386.9,1370 1404.72,1352.18 1404.72,1331.92 ; CN5.1@1122.76,1636.06 JP2.1@1451.06,1636.06 ; JP2.1@1452,1637 1470.95,1655.95 1470.95,1716.7 R37.1@1499.25,1745
TVDD*: JP1.2 R34.1 | length 129
  Top Layer w20: JP1.2@335,1030 339.73,1030 402.08,967.65 402.08,931.52
TVDD_DISCHARGE_EN: R19.2 U15.25 | length 404.9
  Top Layer w6: R19.2@401.53,784.78 448.51,784.78 467.48,803.75 467.48,860.55 534.58,927.66 603.61,927.66 643,888.27 U15.25@697.68,888.27
USB_DM: R11.2 U15.32 | length 536.9
  Top Layer w6: R11.2@250,535 306.4,591.4 458.28,591.4 617.36,750.47 U15.32@697.68,750.47
USB_DP: R12.2 U15.33 | length 471.3
  Top Layer w6: R12.2@307.5,535 344.45,571.95 471.73,571.95 630.56,730.79 U15.33@697.68,730.79
VBUS_PYLK: F1.1 PYLK.A4 PYLK.A9 PYLK.B4 PYLK.B9 U6.5 | length 806.9
  Top Layer w10: PYLK.A4@774.81,309.89 PYLK.B9@786.62,309.89 ; PYLK.B4@963.78,309.88 PYLK.A9@975.6,309.88
  Top Layer w20: U6.5@568.15,310 568.98,309.17 609.58,309.17 v2(610.2,308.55) ; PYLK.B9@781.05,327.56 v4@781.05,371.45 ; PYLK.B4@969,328.77 v4@969,362.58
  Bottom Layer w15: F1.1@490.98,408 490.98,404.75 587.18,308.55 v2(610.2,308.55)
  Bottom Layer w20: v4@977.13,372.01 v4(977.62,372.5)
  Bottom Layer w30: F1.1@490.98,408 744.5,408 v4(780,372.5) ; v4@780.49,372.01 925.68,372.01 ; 925.68,373.41 v4@976.72,373.41
VDD: C27.2 CN3.8 CN7.1 CN7.2 CN7.3 JP2.2 R37.2 U18.7 | length 2610.5
  Top Layer w12: CN3.8@90,2875 164.2,2800.8 U18.7@761.18,2800.8 821.2,2800.8 842,2780 842,2567 1459,1950 CN7.3@1690,1950
  Bottom Layer w20: C27.2@791.5,2780.5 v1(841,2780.5) ; R37.2@1547.03,1745.03 R37.2@1552.03,1745.03 ; JP2.2@1552.03,1637 R37.2@1552.03,1745.03 ; CN7.1@1690,1750 1685.03,1745.03 R37.2@1552.03,1745.03 ; CN7.1@1691,1750 CN7.3@1691,1950
pads on no net: PYLK. PYLK.A8 PYLK.B8 U15.42 U15.45

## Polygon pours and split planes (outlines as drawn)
GND on Bottom Layer "NONET_L-01_P-001" (solid, remove dead copper, pour order 3): 8.64,3928.06 1782.02,3928.06 1782.02,-1 0,-1
GND on Top Layer "NONET_L-01_P-001" (solid, remove dead copper, pour order 4): 8.64,3929.06 1773.49,3929.06 1773.49,0 0,0

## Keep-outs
Keep-Out Layer:
  lines w8: 0,78.74 ccw(c78.74,78.74) 78.74,0 1692.91,0 ccw(c1692.91,78.74) 1771.65,78.74 1771.65,1473.35 ccw(c1730,1473.35) 1730,1515 1630,1515 cw(c1657.5,1542.5) 1630,1570 1730,1570 ccw(c1730,1611.65) 1771.65,1611.65 1771.65,3855.75 1771.65,3879.06 ccw(c1721.65,3879.06) 1721.65,3929.06 1692.91,3929.06 78.74,3929.06 50,3929.06 ccw(c50,3879.06) 0,3879.06 0,3859.09 0,1615 ccw(c43.75,1613.75) 42.5,1570 142.5,1570 cw(c115,1542.5) 142.5,1515 42.5,1515 ccw(c43.75,1471.25) 0,1470 0,78.74 ; 215,1515 cw(c242.5,1542.5) 215,1570 565,1570 585,1570 cw(c557.5,1542.5) 585,1515 565,1515 215,1515 ; 1260,1515 cw(c1287.5,1542.5) 1260,1570 1280,1570 1560,1570 cw(c1532.5,1542.5) 1560,1515 1280,1515 1260,1515

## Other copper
Top Layer:
  pour cut-out: 1655,1370 1665,1370 1665,1360 1655,1360
  pour cut-out: 275,490 285,490 285,480 275,480
  pour cut-out: 275,525 285,525 285,515 275,515
  pour cut-out: 330,525 335.5,525 335.5,503 330,503
  pour cut-out: 330,490 340,490 340,480 330,480
  region net 5V_USB_CHGR: 385,235 395,245 420,245 465,200 510,200 530,180 660,180 660,120 515,120 515,140 490,165 435,165 400,200 385,215
  region net 3V3_PYLK: 240,315 290,315 310,295 355,295 360,290 360,250 345,235 345,165 362.5,147.5 355,140 293.39,140 293.39,153.49 305,165.1 305,230 280,255 240,255
  region net 3V3_PYLK: 1095,155 1105,165 1125,165 1135,155 1135,130 1140,125 1185,125 1190,120 1190,105 1185,100 1130,100 1095,135
  region net 3V3_USB_PYLK: 1227.5,120 1300,120 1315,135 1335,135 1345,125 1345,105 1330,90 1315,90 1290,65 1290,25 1225,25 1225,118.33
  pour cut-out: 390,495 400,495 400,485 390,485
  pour cut-out: 445,495 455,495 455,485 445,485
  pour cut-out: 1627.43,1037 1637.43,1037 1637.43,1027 1627.43,1027
  pour cut-out: 1675,1075 1685,1075 1685,1065 1675,1065

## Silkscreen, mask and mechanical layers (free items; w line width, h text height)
Top Overlay:
  drawing of 1057 lines, arcs and shapes, not listed
  text "USER_PA0" at 136,3534.66 h60
  text "NRST" at 1483,3534.66 h60
  text "1" at 75,3522 h50
  text "28" at 1655.96,3520.54 h50
  text "D1" at 1539,3469 h50
  text "C0" at 193,3458.53 h50
  text "D0" at 1539,3362.54 h50
  text "A0" at 192.96,3358.94 h50
  text "C1" at 1539,3263.54 h50
  text "A1" at 192.96,3259.99 h50
  text "A2" at 192.96,3159.39 h50
  text "C2" at 1539,3152.54 h50
  text "GND" at 193,3059.87 h50
  text "C3" at 1539,3058.54 h50
  text "A3" at 192.96,2961.46 h50
  text "C4" at 1539,2956.54 h50
  text "VDD" at 193,2860.33 h50
  text "C5" at 1539,2859.54 h50
  text "A4" at 192.96,2760.73 h50
  text "C6" at 1539,2760.73 h50
  text "A5" at 192.96,2662.85 h50
  text "C7" at 1539,2657.17 h50
  text "A6" at 192.96,2562.83 h50
  text "B0" at 1539,2555.32 h50
  text "A7" at 192.96,2462.33 h50
  text "B1" at 1540,2462 h50
  text "B2" at 1540,2363.19 h50
  text "B7" at 193,2361 h50
  text "B6" at 193,2262.54 h50
  text "B5" at 1540,2260.17 h50
  text "PY32F005-START V2.0" at 731,2199.78 h60
  text "B3" at 193,2159.54 h50
  text "B4" at 1540,2157.78 h50
  text "15" at 1669,2093.54 h50
  text "14" at 68,2088 h50
  text "2025-12" at 729.96,2076.06 h60
  text "GND" at 175,1933.54 h50
  text "VDD" at 1543,1928 h50
  text "GND" at 174,1834.54 h50
  text "VDD" at 1543,1833 h50
  text "VDD" at 1549,1741 h50
  text "GND" at 173,1730.54 h50
  text "NRST" at 630,1710.54 h50
  text "SWC" at 760,1710.54 h50
  text "GND" at 870,1710.54 h50
  text "SWD" at 985,1710.54 h50
  text "VDD*" at 1100,1710.51 h50
  text "VDD*" at 1377,1701 h40
  text "VDD" at 1507,1698 h40
  text "IDD" at 1607,1624 h40
  text "NRST" at 670,1445.43 h40
  text "SWC" at 790,1445.43 h40
  text "GND" at 896.86,1445.43 h40
  text "SWD" at 996.31,1445.43 h40
  text "VDD*" at 1090,1445.46 h40
  text "DTR" at 896.86,1175.88 h40
  text "TX" at 996.31,1175.88 h40
  text "RX" at 1090,1175.88 h40
  text "SWO" at 670,1175.43 h40
  text "RTS" at 790,1175.43 h40
  text "VDD_SEL" at 493,1088.66 h60
  text "5V" at 208,1075.54 h50
  text "3V3" at 403,1075.54 h50
  text "VDD*" at 282,1075 h50
  text "5V_USB" at 48.18,563.82 h50 r90
  text "CLK" at 1494,423.54 h50
  text "BT0" at 1087,422.54 h50
  text "GND" at 1382,422.54 h50
  text "DIO" at 1292,421.54 h50
  text "VDD" at 1184,421 h50
  text "PY-LINK OB V2.1" at 650,395.78 h60
Bottom Overlay:
Mechanical 1:
  lines w6: 215,1515 565,1515 585,1515 ; 215,1570 565,1570 585,1570 ; 1260,1515 1280,1515 1560,1515 ; 1260,1570 1280,1570 1560,1570
  lines w8: 0,0 ccw(c0,1) 1,1 1,3938.01 ; 215,1515 cw(c242.5,1542.5) 215,1570 ; 585,1515 ccw(c557.5,1542.5) 585,1570 ; 1260,1515 cw(c1287.5,1542.5) 1260,1570 ; 1560,1515 ccw(c1532.5,1542.5) 1560,1570

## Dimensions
1856.64,2.11 to 1850.64,3930.11 on Mechanical 1
42.5,1570 to 78.74,3929.06 on Mechanical 1
78.74,0 to -5,1505 on Mechanical 1
0,0 to 1770,-60 on Mechanical 1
